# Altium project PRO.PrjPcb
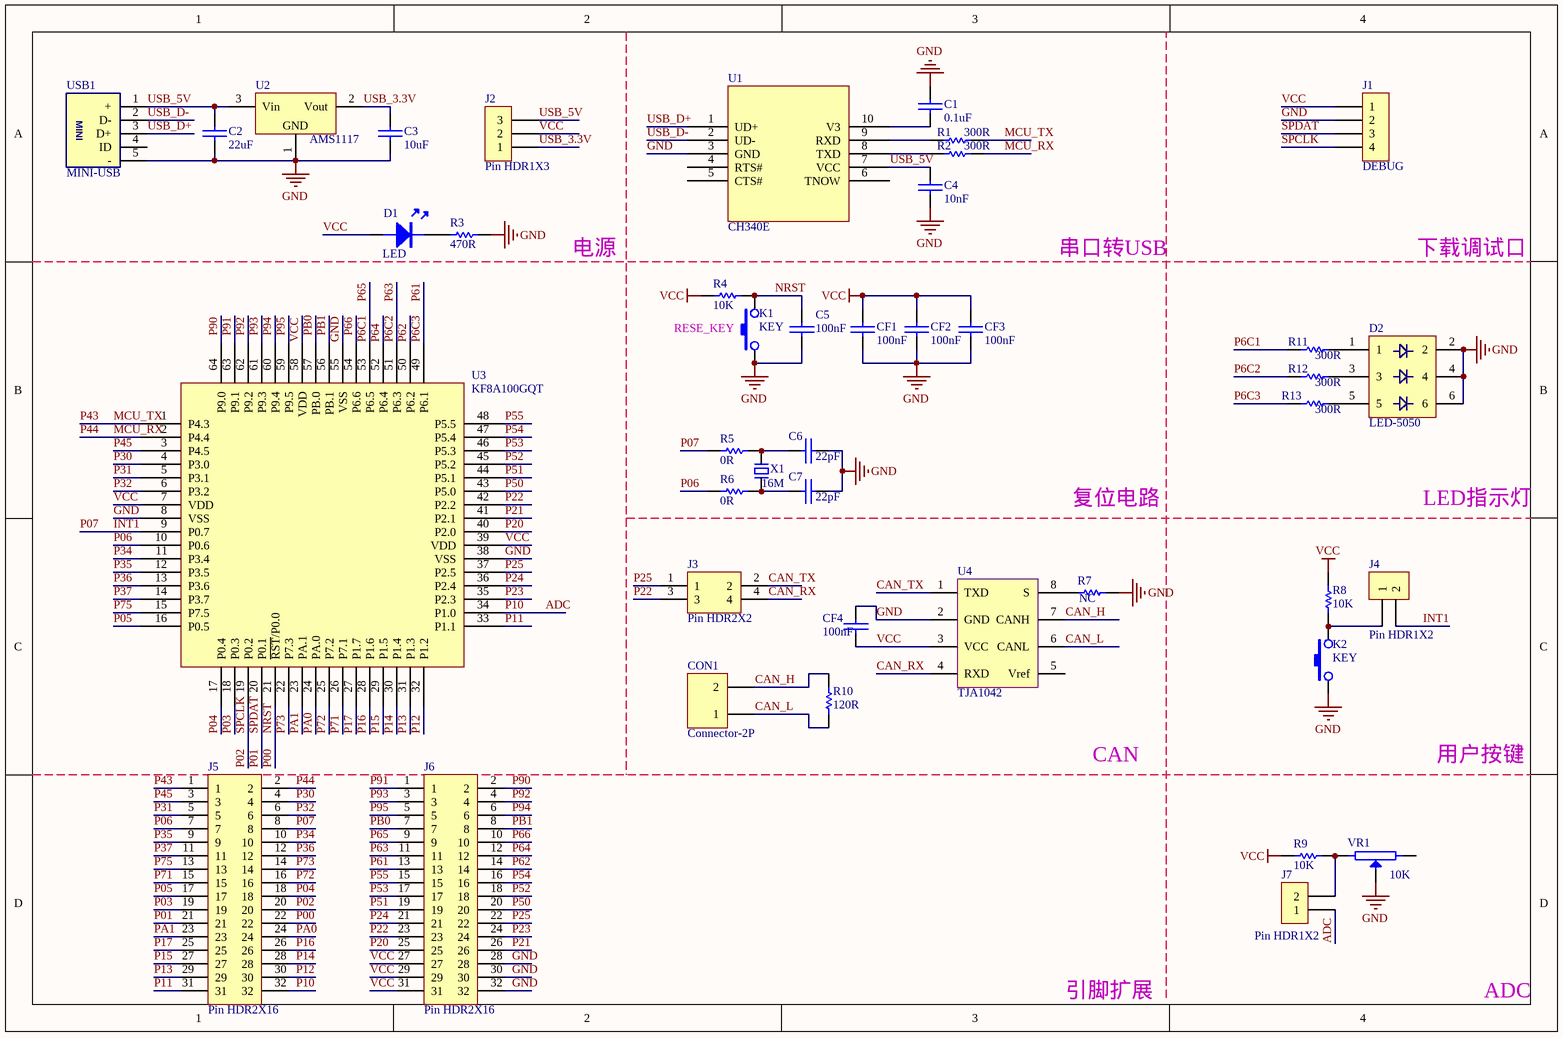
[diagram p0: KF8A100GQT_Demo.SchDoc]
1 sheet, 43 parts. Net scope: global (net labels, ports and power ports of the same name join across sheets).
Board file: KF8A100GQT_Demo.PcbDoc

## Sheet KF8A100GQT_Demo.SchDoc
size A4

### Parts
C1  0.1uF  [0603C]
C2  22uF  [0603C]
C3  10uF  [0603C]
C4  10nF  [0603C]
C5  100nF  [0603C]
C6  22pF  [0603C]
C7  22pF  [0603C]
CF1  100nF  [0603C]
CF2  100nF  [0603C]
CF3  100nF  [0603C]
CF4  100nF  [0603C]
CON1  Connector-2P  [KF2EDG-5.08-2P]
D1  LED  [LED-0603B]
D2  LED-5050  [LED-5050W]
J1  DEBUG  [Pin HDR1X4/2.54mm-S]
J2  Pin HDR1X3  [Pin HDR1X3/2.54mm-S]
J3  Pin HDR2X2  [Pin HDR2X2/2.54mm-S]
J4  Pin HDR1X2  [Pin HDR1X2/2.54mm-S]
J5  Pin HDR2X16  [Pin HDR2X16/2.54mm-S]
J6  Pin HDR2X16  [Pin HDR2X16/2.54mm-S]
J7  Pin HDR1X2  [Pin HDR1X2/2.54mm-S]
K1  KEY  [DIP-6X6X4.3]
K2  KEY  [DIP-6X6X4.3]
R1  300R  [0603R]
R2  300R  [0603R]
R3  470R  [0603R]
R4  10K  [0603R]
R5  0R  [0603R]
R6  0R  [0603R]
R7  NC  [0603R]
R8  10K  [0603R]
R9  10K  [0603R]
R10  120R  [0603R]
R11  300R  [0603R]
R12  300R  [0603R]
R13  300R  [0603R]
U1  CH340E  [MSOP10]
U2  AMS1117  [SOT223]
U3  KF8A100GQT  [LQFP64 7x7]
U4  TJA1042  [SOP8]
USB1  MINI-USB  [USB-MINI-A]
VR1  10K  [3296W]
X1  16M  [OSC HC-49S]

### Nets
GND: C1.2 C2.1 C3.1 C4.1 C5.1 C6.1 C7.1 CF1.1 CF2.1 CF3.1 CF4.2 D2.2 D2.4 D2.6 J1.2 J6.28 J6.30 J6.32 K1.1 K2.1 R3.1 R7.2 U1.3(GND) U2.1(GND) U3.8(VSS) U3.38(VSS) U3.55(VSS) U4.2(GND) USB1.5(-) VR1.2
VCC: CF1.2 CF2.2 CF3.2 CF4.1 D1.A J1.1 J2.2 J6.27 J6.29 J6.31 R4.2 R8.1 R9.1 U3.7(VDD) U3.39(VDD) U3.58(VDD) U4.3(VCC)
ADC: J5.32 J7.1 U3.34(P1.0)  [also labelled P10]
CAN_H: CON1.2 R10.1 U4.7(CANH)
CAN_L: CON1.1 R10.2 U4.6(CANL)
CAN_RX: J3.4 U4.4(RXD)
CAN_TX: J3.2 U4.1(TXD)
INT1: J4.2 J5.8 R5.2 U3.9(P0.7)  [also labelled P07]
MCU_RX: J5.2 R2.1 U3.2(P4.4)  [also labelled P44]
MCU_TX: J5.1 R1.1 U3.1(P4.3)  [also labelled P43]
NRST: C5.2 J5.22 K1.3 R4.1 U3.21(~{RST}/P0.0)  [also labelled P00]
P01: J1.3 J5.21 U3.20(P0.1)  [also labelled SPDAT]
P02: J1.4 J5.20 U3.19(P0.2)  [also labelled SPCLK]
P03: J5.19 U3.18(P0.3)
P04: J5.18 U3.17(P0.4)
P05: J5.17 U3.16(P0.5)
P06: J5.7 R6.2 U3.10(P0.6)
P11: J5.31 U3.33(P1.1)
P12: J5.30 U3.32(P1.2)
P13: J5.29 U3.31(P1.3)
P14: J5.28 U3.30(P1.4)
P15: J5.27 U3.29(P1.5)
P16: J5.26 U3.28(P1.6)
P17: J5.25 U3.27(P1.7)
P20: J6.25 U3.40(P2.0)
P21: J6.26 U3.41(P2.1)
P22: J3.3 J6.23 U3.42(P2.2)
P23: J6.24 U3.35(P2.3)
P24: J6.21 U3.36(P2.4)
P25: J3.1 J6.22 U3.37(P2.5)
P30: J5.4 U3.4(P3.0)
P31: J5.5 U3.5(P3.1)
P32: J5.6 U3.6(P3.2)
P34: J5.10 U3.11(P3.4)
P35: J5.9 U3.12(P3.5)
P36: J5.12 U3.13(P3.6)
P37: J5.11 U3.14(P3.7)
P45: J5.3 U3.3(P4.5)
P50: J6.20 U3.43(P5.0)
P51: J6.19 U3.44(P5.1)
P52: J6.18 U3.45(P5.2)
P53: J6.17 U3.46(P5.3)
P54: J6.16 U3.47(P5.4)
P55: J6.15 U3.48(P5.5)
P61: J6.13 R13.2 U3.49(P6.1)  [also labelled P6C3]
P62: J6.14 U3.50(P6.2)
P63: J6.11 R12.2 U3.51(P6.3)  [also labelled P6C2]
P64: J6.12 U3.52(P6.4)
P65: J6.9 R11.2 U3.53(P6.5)  [also labelled P6C1]
P66: J6.10 U3.54(P6.6)
P71: J5.15 U3.26(P7.1)
P72: J5.16 U3.25(P7.2)
P73: J5.14 U3.22(P7.3)
P75: J5.13 U3.15(P7.5)
P90: J6.2 U3.64(P9.0)
P91: J6.1 U3.63(P9.1)
P92: J6.4 U3.62(P9.2)
P93: J6.3 U3.61(P9.3)
P94: J6.6 U3.60(P9.4)
P95: J6.5 U3.59(P9.5)
PA0: J5.24 U3.24(PA.0)
PA1: J5.23 U3.23(PA.1)
PB0: J6.7 U3.57(PB.0)
PB1: J6.8 U3.56(PB.1)
USB_3.3V: C3.2 J2.1 U2.2(Vout)
USB_5V: C2.2 C4.2 J2.3 U1.7(VCC) U2.3(Vin) USB1.1(+)
USB_D+: U1.1(UD+) USB1.3(D+)
USB_D-: U1.2(UD-) USB1.2(D-)
NetC1_1: C1.1 U1.10(V3)
NetC6_2: C6.2 R5.1 X1.2
NetC7_2: C7.2 R6.1 X1.1
NetD1_K: D1.K R3.2
NetD2_1: D2.1 R11.1
NetD2_3: D2.3 R12.1
NetD2_5: D2.5 R13.1
NetJ4_1: J4.1 K2.3 R8.2
NetJ7_2: J7.2 R9.2 VR1.3
NetR1_2: R1.2 U1.9(RXD)
NetR2_2: R2.2 U1.8(TXD)
NetR7_1: R7.1 U4.8(S)

Not connected (* = marked no-connect by the designer): U1 4(RTS#) 5(CTS#) 6(TNOW); U4 5(Vref); USB1 4(ID); VR1 1

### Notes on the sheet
- 电源
- 串口转USB
- 下载调试口
- RESE_KEY
- 复位电路
- LED指示灯
- CAN
- 用户按键
- 引脚扩展
- ADC

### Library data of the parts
C1-C7 CF1-CF4 = CAP: 无极性电容
J1 = Pin HDR1X4
R1-R13 = RES
U1 = CH340E: USB to TTL Serial / UART
U2 = AMS1117: 三端稳压芯片
U3 = KF8A100GQT: QPF64
U4 = TJA1050
VR1 = RESVR
X1 = XTAL-2P: 2脚无源脚晶振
